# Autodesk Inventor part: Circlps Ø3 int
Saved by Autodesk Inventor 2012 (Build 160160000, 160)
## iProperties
Created: 2012-11
Part Number: Circlps Ø3 int
Material: Default
Document SubType Name: Modeling
Designer: Administrateur
Density: 1 g/cm^3
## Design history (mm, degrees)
node "Circlps Ø3 int1"
node "Circlps Ø3 int"
node "Base1"
